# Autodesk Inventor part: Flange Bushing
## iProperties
Title: Flange Bushing
Subject: "Boston Gear" flanged bronze bushing
Author: sbraun
Comments: Boston Gear oil impregnated, flanged series bronze bushings "Bost-Bronz" series pg 14-15
Shininess: 20.0
PropertySet Name: _Private Model Information
Created: 2001-02
Part Number: FB58-5
Material: Bronze, Soft Tin
Document SubType Name: Modeling
Designer: sbraun
Control State: 0
Master: False
Checked Out: False
PropertySet Name: Design Tracking Control
Density: 8.874
Volumn: 4.725838973020256
Area: 33.569370490209224
PropertySet Name: Model Information
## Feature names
1. bushing [Extrusion]
2. flange [Extrusion]
